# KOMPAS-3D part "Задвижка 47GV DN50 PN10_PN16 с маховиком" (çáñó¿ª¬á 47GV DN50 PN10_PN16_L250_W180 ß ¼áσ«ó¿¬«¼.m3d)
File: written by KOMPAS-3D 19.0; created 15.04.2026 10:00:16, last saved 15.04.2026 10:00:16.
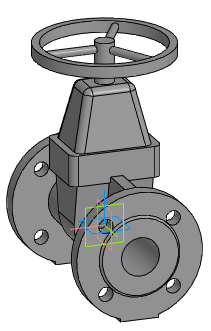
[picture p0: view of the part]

Document properties: Автор: Евгений; Полное имя файла: Z:\3.Личные\kachalov\3d для проектировщиков\2.1 Тип 47GV, 47GV.Z\Задвижка 47GV_DN40-DN600\stp_Задвижка 47GV\Задвижка 47GV DN50 PN10_PN16_L250_W180 с маховиком.m3d

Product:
- Part/product: Задвижка 47GV DN50 PN10_PN16 с маховиком

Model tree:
1. Операция без истории:1  (labels: Задвижка 47GV DN50 PN10_PN16 с маховиком)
